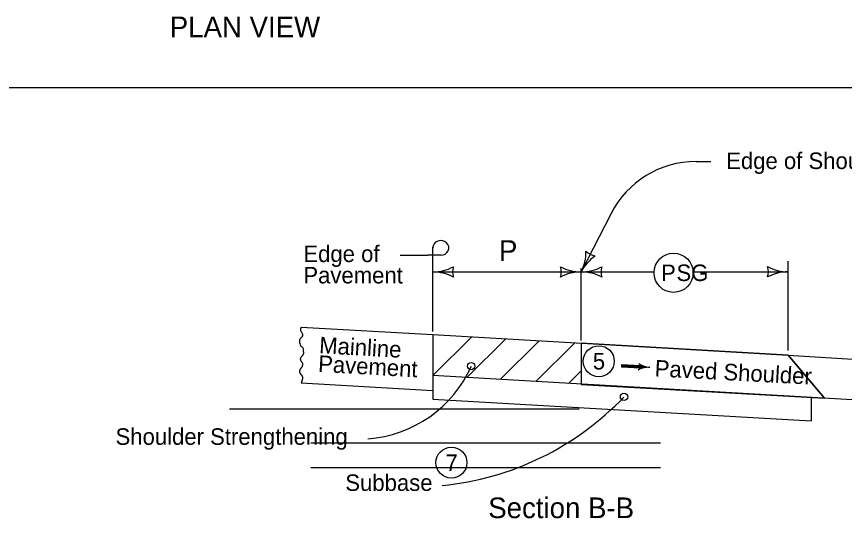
# Model space of a CAD drawing. Extents: x 10133 to 81668, y 5848 to 11018.
# Drawn here: x 11006 to 11807, y 8939 to 9425 of the extents above; entities that cross this region are included whole.
import ezdxf

# ---------------------------------------------------------------- set-up
doc = ezdxf.new("R2010")
doc.units = 0
for name, color, linetype in [('dsnStdLabel', 7, 'Continuous'), ('dsnStdLineWork', 7, 'Continuous'), ('dsnStdNote', 7, 'Continuous'), ('dsnStdSection', 7, 'Continuous'), ('dsnStdShading', 7, 'Continuous'), ('Level 5', 7, 'Continuous'), ('PlanSheetShape', 7, 'Continuous'), ('SheetText', 7, 'Continuous')]:
    doc.layers.add(name, color=color, linetype=linetype)

msp = doc.modelspace()

# ---------------------------------------------------------------- linework, layer by layer
at = {"layer": 'dsnStdLabel'}
for centre in [(11569.5, 9091.41), (11426.79, 8993.21)]:
    msp.add_circle(centre, 15, dxfattribs=at)
at = {"layer": 'dsnStdLineWork'}
for p, q in [((11281.22, 9124.58), (11408.68, 9117.17)), ((11408.68, 9117.17), (11408.68, 9063.16)), ((11408.68, 9117.17), (11752.97, 9097.15)), ((11552.45, 9108.8), (11552.45, 9069)), ((11752.52, 9097.34), (11752.52, 9097.34)), ((11752.97, 9097.15), (11788.01, 9055.7)), ((11752.98, 9097.23), (11887.73, 9088.85)), ((11984.79, 9044.35), (11408.68, 9077.58)), ((11281.25, 9070.57), (11408.68, 9063.16)), ((11775.21, 9070.85), (11775.21, 9070.85)), ((11408.68, 9063.16), (11408.68, 9054.74)), ((11408.68, 9054.74), (11775.21, 9033.6)), ((11775.21, 9056.43), (11775.21, 9033.6)), ((11211.96, 9045.23), (11550.46, 9045.23)), ((11290.63, 9012.25), (11629.13, 9012.25)), ((11290.63, 8988.58), (11629.13, 8988.58))]:
    msp.add_line(p, q, dxfattribs=at)
for points in [[(11281.22, 9124.58), (11280.71, 9120.98), (11281.76, 9119.47), (11282.62, 9117.18), (11282.01, 9115.12), (11280.11, 9112.74), (11279.59, 9110.84), (11280.11, 9108.54), (11280.98, 9106.17), (11282.01, 9105.45), (11283.4, 9102.92), (11283.39, 9102.08)], [(11281.43, 9084.97), (11281.64, 9085.22), (11281.84, 9085.48), (11282.19, 9086.04), (11282.47, 9086.63), (11282.59, 9086.93), (11282.69, 9087.25), (11282.82, 9087.87), (11282.87, 9088.49), (11282.82, 9089.08), (11282.76, 9089.35), (11282.72, 9089.49), (11282.68, 9089.62), (11282.47, 9090), (11282.19, 9090.36), (11281.89, 9090.73), (11281.64, 9091.12), (11281.5, 9091.41), (11281.36, 9091.69), (11281.1, 9092.26), (11280.9, 9092.83), (11280.83, 9093.12), (11280.77, 9093.42), (11280.76, 9093.55), (11280.76, 9093.67), (11280.91, 9094.45), (11281.12, 9094.97), (11281.38, 9095.48), (11281.82, 9096.12), (11282.34, 9096.66), (11282.86, 9097.21), (11283.09, 9097.51), (11283.29, 9097.86), (11283.49, 9098.33), (11283.65, 9098.8), (11283.75, 9099.28), (11283.78, 9099.52), (11283.8, 9099.64), (11283.81, 9099.76), (11283.76, 9100.26), (11283.61, 9100.78), (11283.56, 9100.91), (11283.5, 9101.03), (11283.45, 9101.16), (11283.43, 9101.29), (11283.39, 9102.08)], [(11281.43, 9084.97), (11281.21, 9084.73), (11280.97, 9084.5), (11280.73, 9084.26), (11280.55, 9083.99), (11280.41, 9083.7), (11280.27, 9083.42), (11280.01, 9082.85), (11279.9, 9082.56), (11279.8, 9082.28), (11279.73, 9081.98), (11279.7, 9081.84), (11279.68, 9081.69), (11279.69, 9081.17), (11279.82, 9080.66), (11280.03, 9080.14), (11280.29, 9079.63), (11280.73, 9078.99), (11281.25, 9078.45), (11281.77, 9077.9), (11282, 9077.6), (11282.2, 9077.26), (11282.6, 9076.31), (11282.71, 9075.83), (11282.72, 9075.36), (11282.68, 9075.07), (11282.63, 9074.78), (11282.58, 9074.49), (11282.51, 9074.21), (11282.2, 9073.06), (11282.02, 9072.45), (11281.82, 9071.85), (11281.6, 9071.26), (11281.47, 9070.97), (11281.33, 9070.68), (11281.25, 9070.57)]]:
    msp.add_spline(points, degree=3, dxfattribs=at)
at = {"layer": 'dsnStdNote'}
for centre in [(11445.98, 9086.76), (11445.98, 9086.76), (11593.92, 9056.91), (11593.92, 9056.91)]:
    msp.add_circle(centre, 3.54, dxfattribs=at)
at = {"layer": 'dsnStdShading'}
msp.add_line((12307.76, 9356.36), (10152.18, 9356.36), dxfattribs=at)
at = {"layer": 'Level 5'}
msp.add_circle((11569.5, 9091.41), 15, dxfattribs=at)
at = {"layer": 'PlanSheetShape'}
for p, q in [((11552.49, 9108.81), (11552.45, 9069)), ((11752.98, 9097.23), (11552.49, 9108.81)), ((11788.01, 9055.7), (11752.98, 9097.23)), ((11552.45, 9069), (11788.01, 9055.7))]:
    msp.add_line(p, q, dxfattribs=at)
at = {"layer": 'SheetText'}
for p, q in [((11663.64, 9284.83), (11677.95, 9284.83)), ((11581.34, 9234.46), (11552.44, 9177.9)), ((11408.68, 9181.22), (11408.68, 9202.08)), ((11377.31, 9194.07), (11403.99, 9194.07)), ((11416.49, 9194.07), (11403.99, 9194.07)), ((11752.98, 9101.79), (11752.98, 9188.45)), ((11408.68, 9120.31), (11408.68, 9181.22)), ((11552.44, 9111.66), (11552.44, 9181.22)), ((11408.68, 9177.9), (11623, 9177.9)), ((11660.83, 9178.05), (11752.98, 9178.05)), ((11408.68, 9077.57), (11446.48, 9114.97)), ((11441.72, 9075.66), (11479.51, 9113.07)), ((11473.96, 9073.81), (11511.75, 9111.21)), ((11508.57, 9071.81), (11546.36, 9109.21)), ((11609.71, 9086.06), (11591.5, 9087.11)), ((11609.61, 9085.12), (11609.61, 9085.12)), ((11609.72, 9087.07), (11609.72, 9087.07)), ((11540.19, 9069.99), (11552.45, 9082.12))]:
    msp.add_line(p, q, dxfattribs=at)
for points in [[(11609.74, 9087), (11591.57, 9088.05), (11591.44, 9086.17), (11609.61, 9085.12), (11609.66, 9086.73), (11591.79, 9087.83), (11591.73, 9086.33), (11609.22, 9085.38), (11609.35, 9086.5), (11592.02, 9087.56), (11592, 9086.56), (11609.01, 9085.58), (11609.1, 9086.29), (11592.21, 9087.34), (11592.2, 9086.78), (11608.8, 9085.84)], [(11609.33, 9088.26), (11610.03, 9087.09), (11610, 9085.44), (11609.24, 9084.05), (11612, 9084.91), (11615.19, 9085.56), (11616.09, 9085.7), (11613.85, 9086.24), (11610.62, 9087.47), (11609.68, 9088.01), (11609.8, 9084.49), (11614.75, 9085.71), (11610.11, 9087.29), (11610.12, 9084.87), (11613.52, 9085.8), (11610.52, 9086.66), (11610.29, 9085.28), (11612.45, 9085.78), (11610.86, 9086.29), (11610.72, 9085.63), (11611.51, 9085.79)]]:
    msp.add_lwpolyline(points, dxfattribs=at)
msp.add_circle((11641.92, 9177.08), 18.93, dxfattribs=at)
for centre, radius, start, end in [((11663.64, 9192.4), 92.43, 90, 152.9341), ((11514.59, 9197.24), 42.5, 332.9341, 1.00659), ((11568.65, 9209.63), 16.42, 225.20075, 260.66745), ((11590.28, 9158.56), 42.5, 124.86161, 152.9341), ((11408.68, 9220.4), 42.5, 270, 298.07249), ((11444.32, 9177.9), 16.42, 162.26665, 197.73335), ((11516.8, 9177.9), 16.42, 342.26665, 17.73335), ((11552.44, 9220.4), 42.5, 241.92751, 270), ((11552.44, 9220.4), 42.5, 270, 298.07249), ((11588.07, 9177.9), 16.42, 162.26665, 197.73335), ((11717.34, 9178.05), 16.42, 342.26665, 17.73335), ((11752.98, 9220.55), 42.5, 241.92751, 270), ((11408.68, 9135.4), 42.5, 61.92751, 90), ((11552.44, 9135.4), 42.5, 90, 118.07249), ((11552.44, 9135.4), 42.5, 61.92751, 90), ((11752.98, 9135.55), 42.5, 90, 118.07249), ((11337.43, 9134.93), 118.88, 274.08506, 336.06992), ((11389.97, 9251.67), 282.03, 275.67842, 316.28441)]:
    msp.add_arc(centre, radius, start, end, dxfattribs=at)
for centre, major_axis, start_param, end_param in [((11416.49, 9201.2), (-7.81, 0), 1.570796, 6.283185), ((11605.94, 9086.28), (3.88, 0), 5.202895, 7.237436), ((11618.21, 9065.28), (22.17, 0), 1.537172, 2.061295), ((11621, 9105.7), (-22.17, 0), 0.954258, 1.478381)]:
    msp.add_ellipse(centre, major_axis=major_axis, ratio=0.913811, start_param=start_param, end_param=end_param, dxfattribs=at)

# ---------------------------------------------------------------- texts
at = {"layer": 'dsnStdLabel'}
for s, p in [('5', (11563.73, 9083.41)), ('7', (11421.08, 8985.21))]:
    msp.add_text(s, height=16, dxfattribs=at).set_placement(p)
at = {"layer": 'dsnStdSection'}
msp.add_text('PLAN VIEW', height=20, dxfattribs=at).set_placement((11154.04, 9405.26))
msp.add_text('PLAN VIEW', height=20, dxfattribs=at).set_placement((11154.04, 9405.26))
at = {"layer": 'SheetText'}
for s, height, p in [('Edge of Shoulder Strengthening', 16, (11692.84, 9277.59)), ('Edge of ', 16, (11283.43, 9187.48)), ('P', 20, (11472.84, 9188.64)), ('Pavement', 16, (11283.43, 9166.78)), ('P', 16, (11629.79, 9169.08)), ('SG', 16, (11644.71, 9169.08)), ('Shoulder Strengthening', 16, (11101.54, 9010.47)), ('Subbase', 16, (11324.05, 8965.83)), ('Section B-B', 20, (11462.44, 8939.46))]:
    msp.add_text(s, height=height, dxfattribs=at).set_placement(p)
for s, rotation, p in [('Mainline', 356.73462, (11298.44, 9099.24)), ('Pavement', 356.73462, (11297.41, 9081.27)), ('Paved Shoulder ', 356.98301, (11623.32, 9076.79))]:
    msp.add_text(s, height=16, rotation=rotation, dxfattribs=at).set_placement(p)

doc.saveas('drawing.dxf')
